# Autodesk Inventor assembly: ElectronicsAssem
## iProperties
Shininess: 64.0
Length Units: 11272
Angle Units: 11279
Time Units: 11290
Mass Units: 11286
Length Display Precision: 3
Angle Display Precision: 2
Compacted: True
Part Number: ElectronicsAssem
Document SubType Name: Assembly
Created: 2006-08
Designer: jpalmisano
Manufacturer: Standard
Standards Organization: Custom
Mass: 34 g
Surface Area: 203.831 cm^2
Volume: 14.7081 cm^3
Density: 2.31165 g/cm^3
Density: 0.0
Volumn: 0.0
Area: 0.0
PropertySet Name: Model Information
Control State: 0
Master: False
Checked Out: False
Author: jpalmisano
